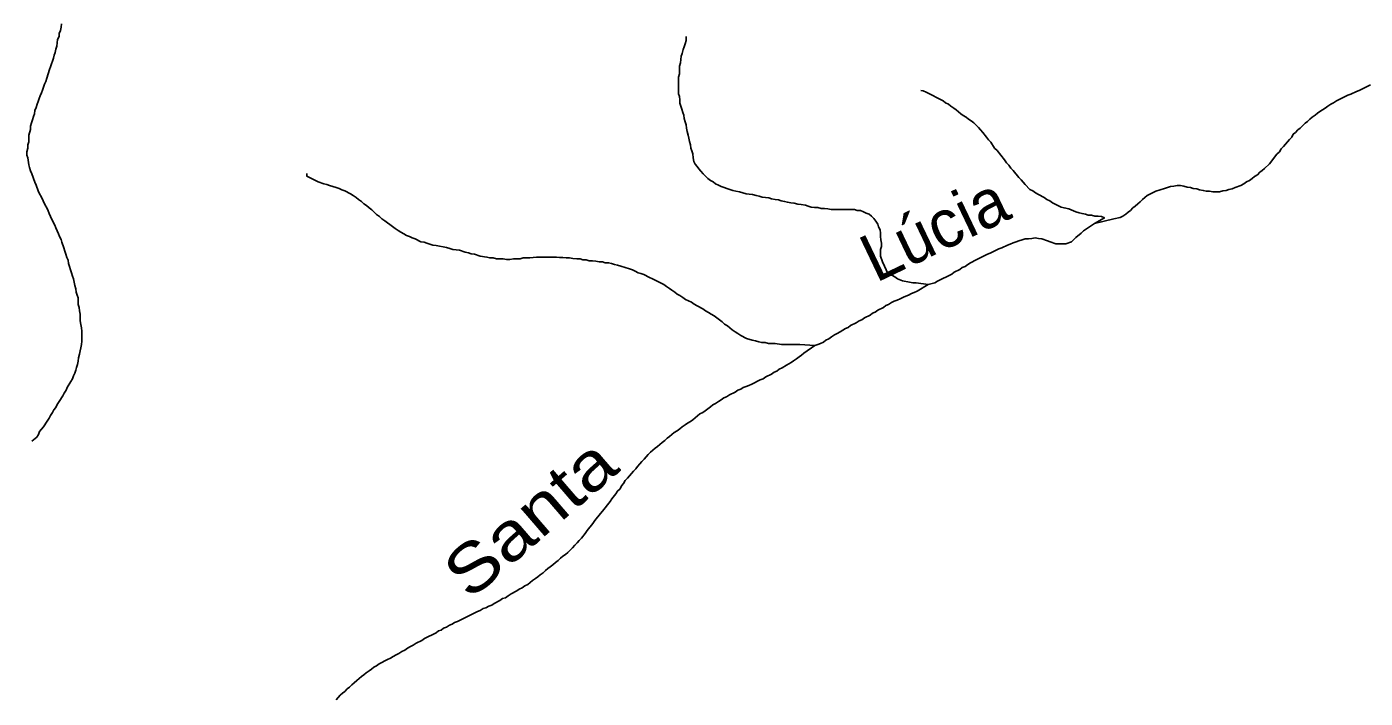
# Model space of a CAD drawing. Extents: x 652.3 to 678, y 7316.9 to 7344.9.
# Drawn here: x 670.317 to 672.557, y 7341.527 to 7342.649 of the extents above; entities that cross this region are included whole.
import ezdxf
from ezdxf.enums import TextEntityAlignment as Align

# ---------------------------------------------------------------- set-up
doc = ezdxf.new("R2010")
doc.units = 0
doc.header["$LTSCALE"] = 0.032
doc.layers.add('61', color=7, linetype='Continuous')
doc.layers.add('7', color=7, linetype='Continuous', lineweight=25)

msp = doc.modelspace()

# ---------------------------------------------------------------- linework, layer by layer
at = {"layer": '7'}
for points in [[(670.375, 7342.6543), (670.3742, 7342.6488), (670.3734, 7342.6432), (670.371, 7342.6384), (670.371, 7342.6329), (670.3686, 7342.6281), (670.3678, 7342.6225), (670.367, 7342.6169), (670.3654, 7342.6122), (670.3646, 7342.6066), (670.363, 7342.6018), (670.3614, 7342.597), (670.3567, 7342.5827), (670.3551, 7342.578), (670.3503, 7342.5636), (670.3487, 7342.5581), (670.3463, 7342.5533), (670.3447, 7342.5485)], [(671.4205, 7342.6333), (671.4205, 7342.6329), (671.4205, 7342.6313), (671.4205, 7342.6297), (671.4205, 7342.6281), (671.4205, 7342.6265), (671.4189, 7342.6209), (671.4173, 7342.6161), (671.4157, 7342.6114), (671.4141, 7342.605), (671.4125, 7342.6002), (671.4117, 7342.5947), (671.411, 7342.5891), (671.4094, 7342.5835), (671.4094, 7342.5764), (671.4094, 7342.5708), (671.4078, 7342.5652)], [(671.4078, 7342.5652), (671.4078, 7342.5596), (671.4078, 7342.5541), (671.4078, 7342.5485), (671.4078, 7342.5429), (671.4078, 7342.5374), (671.4094, 7342.5326), (671.4102, 7342.527), (671.4102, 7342.5215), (671.4117, 7342.5167), (671.4133, 7342.5119), (671.4149, 7342.5063), (671.4165, 7342.5016), (671.4173, 7342.496), (671.4189, 7342.4904), (671.4205, 7342.4857), (671.4213, 7342.4801), (671.4221, 7342.4745), (671.4237, 7342.4681), (671.4253, 7342.4634), (671.4261, 7342.4578), (671.4277, 7342.4522), (671.4285, 7342.4467), (671.43, 7342.4419), (671.4316, 7342.4371), (671.4324, 7342.43), (671.4332, 7342.4244), (671.4356, 7342.4196), (671.4388, 7342.4156), (671.442, 7342.4117), (671.4452, 7342.4077), (671.4491, 7342.4037), (671.4531, 7342.3997), (671.4571, 7342.3957), (671.4611, 7342.3926), (671.4659, 7342.3902), (671.4698, 7342.387), (671.4746, 7342.3846), (671.4794, 7342.3822), (671.4842, 7342.3806), (671.4889, 7342.379), (671.4937, 7342.3774), (671.4985, 7342.3758), (671.504, 7342.3743), (671.5096, 7342.3735), (671.5152, 7342.3719), (671.5208, 7342.3703), (671.5263, 7342.3695), (671.5319, 7342.3687), (671.5375, 7342.3671), (671.543, 7342.3663), (671.5478, 7342.3647), (671.5534, 7342.3639), (671.5589, 7342.3631), (671.5637, 7342.3615), (671.5693, 7342.3607), (671.5749, 7342.3599), (671.5796, 7342.3583), (671.5852, 7342.3575), (671.59, 7342.356), (671.5956, 7342.3552), (671.6011, 7342.3544), (671.6075, 7342.3528), (671.6131, 7342.352), (671.6202, 7342.3512), (671.625, 7342.3496), (671.6298, 7342.348), (671.6353, 7342.3472), (671.6409, 7342.3472), (671.6465, 7342.3456), (671.652, 7342.3456), (671.6576, 7342.3448), (671.6632, 7342.344), (671.6688, 7342.344), (671.6743, 7342.344), (671.6799, 7342.344), (671.6855, 7342.344), (671.691, 7342.344), (671.6966, 7342.344), (671.7022, 7342.344), (671.7069, 7342.3424), (671.7125, 7342.3424), (671.7173, 7342.34), (671.7221, 7342.3377), (671.7268, 7342.3361), (671.7308, 7342.3329), (671.7348, 7342.3289), (671.738, 7342.3241), (671.7412, 7342.3194), (671.7428, 7342.3146), (671.7451, 7342.3098), (671.7459, 7342.3042), (671.7459, 7342.2987), (671.7467, 7342.2931), (671.7475, 7342.2875), (671.7475, 7342.282), (671.7459, 7342.2772), (671.7459, 7342.2716), (671.7459, 7342.266), (671.7491, 7342.2565), (671.7587, 7342.2358)], [(670.3447, 7342.5485), (670.3431, 7342.5437), (670.3415, 7342.539), (670.3392, 7342.5342), (670.3376, 7342.5294), (670.336, 7342.5246), (670.3344, 7342.5199), (670.3328, 7342.5143), (670.3304, 7342.5095), (670.3296, 7342.504), (670.328, 7342.4992), (670.3264, 7342.4936), (670.3248, 7342.4888), (670.3232, 7342.4833), (670.3232, 7342.4777), (670.3201, 7342.4681), (670.3201, 7342.457), (670.3185, 7342.4522), (670.3185, 7342.4467), (670.3169, 7342.4403), (670.3169, 7342.4347), (670.3185, 7342.43), (670.3201, 7342.4188), (670.3217, 7342.414), (670.3232, 7342.4085), (670.3256, 7342.4037), (670.3304, 7342.3894), (670.3328, 7342.3846), (670.336, 7342.375), (670.3384, 7342.3703), (670.3408, 7342.3655), (670.3479, 7342.3512), (670.3503, 7342.3464), (670.3527, 7342.3416), (670.3543, 7342.3369), (670.3567, 7342.3321), (670.3591, 7342.3273), (670.3638, 7342.3178), (670.3654, 7342.313), (670.3678, 7342.3082), (670.3702, 7342.3034), (670.3718, 7342.2987), (670.3742, 7342.2939), (670.3758, 7342.2891), (670.3789, 7342.2796), (670.3805, 7342.274), (670.3821, 7342.2692), (670.3837, 7342.2637), (670.3861, 7342.2589), (670.3869, 7342.2533), (670.3885, 7342.2485), (670.3901, 7342.243), (670.3917, 7342.2382), (670.3933, 7342.2326), (670.3949, 7342.2278), (670.3964, 7342.2223), (670.3972, 7342.2167), (670.3988, 7342.2111), (670.3996, 7342.2056), (670.4012, 7342.2008), (670.4028, 7342.196), (670.4028, 7342.1849), (670.4044, 7342.1801), (670.4052, 7342.1745), (670.406, 7342.169), (670.406, 7342.1578), (670.4076, 7342.1515), (670.4084, 7342.1459), (670.4092, 7342.1403), (670.4092, 7342.1236), (670.4084, 7342.118), (670.4076, 7342.1125), (670.406, 7342.1077), (670.4052, 7342.1021), (670.4036, 7342.0958), (670.4028, 7342.0902), (670.402, 7342.0846), (670.4004, 7342.0798), (670.3988, 7342.0751), (670.3972, 7342.0703), (670.3949, 7342.0655), (670.3933, 7342.0608), (670.3909, 7342.056), (670.3845, 7342.0464), (670.3829, 7342.0417), (670.3797, 7342.0369), (670.3774, 7342.0321), (670.371, 7342.0226), (670.3678, 7342.0178), (670.3654, 7342.013), (670.3622, 7342.009), (670.3598, 7342.0043), (670.3567, 7341.9995), (670.3543, 7341.9947), (670.3511, 7341.9899), (670.3447, 7341.9804), (670.3384, 7341.9724), (670.3368, 7341.9677), (670.3336, 7341.9629), (670.3256, 7341.9565), (670.3253, 7341.9563)], [(672.1041, 7342.3206), (672.1207, 7342.3297), (672.1159, 7342.3321), (672.1104, 7342.3329), (672.1048, 7342.3329), (672.0992, 7342.3345), (672.0937, 7342.3345), (672.0889, 7342.3361), (672.0833, 7342.3369), (672.0785, 7342.3384), (672.073, 7342.34), (672.061, 7342.3448), (672.0531, 7342.3464), (672.0483, 7342.348), (672.034, 7342.3552), (672.0292, 7342.3583), (672.0244, 7342.3607), (672.0197, 7342.3639), (672.0101, 7342.3687), (672.0053, 7342.3719), (672.0006, 7342.375), (671.9958, 7342.3774), (671.9878, 7342.3854), (671.9846, 7342.3894), (671.9815, 7342.3934), (671.9775, 7342.3973), (671.9679, 7342.4093), (671.964, 7342.4132), (671.9608, 7342.418), (671.9568, 7342.422), (671.9536, 7342.4268), (671.9409, 7342.4427), (671.9369, 7342.4467), (671.9305, 7342.4562), (671.9266, 7342.4602), (671.9234, 7342.465), (671.917, 7342.4729), (671.913, 7342.4769), (671.9098, 7342.4809), (671.9059, 7342.4849), (671.9019, 7342.4888), (671.8979, 7342.492), (671.8931, 7342.4952), (671.8892, 7342.4984), (671.8844, 7342.5008), (671.8804, 7342.504), (671.8764, 7342.5071), (671.8725, 7342.5103), (671.8685, 7342.5135), (671.8637, 7342.5167), (671.8597, 7342.5199), (671.8549, 7342.5223), (671.851, 7342.5254), (671.8223, 7342.5398), (671.8175, 7342.5421), (671.8136, 7342.5429), (671.8132, 7342.543)], [(672.1041, 7342.3206), (672.1366, 7342.3281), (672.147, 7342.3305), (672.1517, 7342.3329), (672.1565, 7342.3361), (672.1605, 7342.3392), (672.1645, 7342.3424), (672.1684, 7342.3464), (672.1724, 7342.3496), (672.1764, 7342.3536), (672.1804, 7342.3567), (672.1844, 7342.3607), (672.1883, 7342.3639), (672.1923, 7342.3671), (672.2066, 7342.3743), (672.221, 7342.379), (672.2265, 7342.3806), (672.2313, 7342.3822), (672.2369, 7342.383), (672.2424, 7342.3838), (672.248, 7342.3838), (672.2536, 7342.383), (672.2592, 7342.3814), (672.2647, 7342.3806), (672.2695, 7342.379), (672.2751, 7342.3782), (672.2798, 7342.3766), (672.2862, 7342.3758), (672.291, 7342.3743), (672.2966, 7342.3743), (672.3021, 7342.3735), (672.3133, 7342.3735), (672.3188, 7342.375), (672.3244, 7342.3758), (672.3292, 7342.3774), (672.3347, 7342.3782), (672.3395, 7342.3806), (672.3491, 7342.3838), (672.3538, 7342.387), (672.3586, 7342.3902), (672.3634, 7342.3926), (672.3682, 7342.3957), (672.3721, 7342.3989), (672.3769, 7342.4021), (672.3809, 7342.4061), (672.3849, 7342.4093), (672.3889, 7342.4124), (672.3968, 7342.4204), (672.4095, 7342.4363), (672.4135, 7342.4403), (672.4167, 7342.4451), (672.4207, 7342.449), (672.4239, 7342.453), (672.427, 7342.457), (672.4302, 7342.461), (672.4342, 7342.465), (672.4366, 7342.4697), (672.4406, 7342.4729), (672.4446, 7342.4769), (672.4485, 7342.4801), (672.4565, 7342.488), (672.4605, 7342.4912), (672.4644, 7342.4952), (672.4684, 7342.4984), (672.4732, 7342.5016), (672.4772, 7342.5047), (672.4812, 7342.5079), (672.4859, 7342.5103), (672.4899, 7342.5135), (672.4947, 7342.5167), (672.4995, 7342.5199), (672.5042, 7342.5223), (672.509, 7342.5254), (672.5281, 7342.535), (672.5329, 7342.5366), (672.5424, 7342.5413), (672.5472, 7342.5429), (672.5663, 7342.5525)], [(670.7855, 7342.4041), (670.7855, 7342.3997), (670.8046, 7342.3902), (670.8142, 7342.387), (670.819, 7342.3854), (670.8237, 7342.3838), (670.8349, 7342.3806), (670.8396, 7342.379), (670.8444, 7342.3766), (670.8492, 7342.375), (670.8587, 7342.3703), (670.8635, 7342.3671), (670.8683, 7342.3639), (670.8723, 7342.3607), (670.877, 7342.3575), (670.881, 7342.3536), (670.8858, 7342.3504), (670.8898, 7342.3464), (670.8945, 7342.3432), (670.9025, 7342.3353), (670.9073, 7342.3321), (670.9113, 7342.3281), (670.916, 7342.3249), (670.9208, 7342.3217), (670.9248, 7342.3186), (670.9288, 7342.3154), (670.9335, 7342.3122), (670.9383, 7342.309), (670.9431, 7342.3058), (670.9479, 7342.3034), (670.9526, 7342.3003), (670.9574, 7342.2987), (670.9622, 7342.2963)], [(671.8255, 7342.2183), (671.8366, 7342.2215), (671.8414, 7342.2239), (671.8653, 7342.2358), (671.8693, 7342.239), (671.8788, 7342.2438), (671.8828, 7342.2469), (671.8876, 7342.2485), (671.8923, 7342.2517), (671.8963, 7342.2549), (671.9059, 7342.2597), (671.9106, 7342.2621), (671.925, 7342.2692), (671.9297, 7342.2708), (671.9441, 7342.278), (671.9488, 7342.2796), (671.9584, 7342.2843), (671.9632, 7342.2859), (671.9679, 7342.2883), (671.9727, 7342.2899), (671.9775, 7342.2915), (671.9831, 7342.2931), (671.9878, 7342.2947), (671.9934, 7342.2947), (671.999, 7342.2955), (672.0045, 7342.2963), (672.0101, 7342.2955), (672.0157, 7342.2947), (672.0252, 7342.2915), (672.03, 7342.2899), (672.0395, 7342.2867), (672.0563, 7342.2867), (672.0658, 7342.2899), (672.073, 7342.2971), (672.0817, 7342.3042), (672.0857, 7342.3082), (672.1041, 7342.3206)], [(670.9622, 7342.2963), (670.967, 7342.2947), (670.9765, 7342.2899), (670.9821, 7342.2891), (670.9868, 7342.2875), (670.9964, 7342.2843), (671.002, 7342.2835), (671.0075, 7342.2828), (671.0139, 7342.2812), (671.0195, 7342.2804), (671.025, 7342.2788), (671.0298, 7342.2772), (671.0354, 7342.2764), (671.041, 7342.2756), (671.0505, 7342.2724), (671.0561, 7342.2716), (671.0608, 7342.27), (671.0664, 7342.2692), (671.076, 7342.266), (671.0871, 7342.2644), (671.0919, 7342.2629), (671.0975, 7342.2629), (671.103, 7342.2613), (671.1142, 7342.2613), (671.1197, 7342.2605), (671.1253, 7342.2605), (671.1317, 7342.2613), (671.1428, 7342.2613), (671.1476, 7342.2629), (671.1587, 7342.2629), (671.1643, 7342.2637), (671.1699, 7342.2644), (671.2033, 7342.2644), (671.2088, 7342.2637), (671.2144, 7342.2637), (671.22, 7342.2629), (671.2256, 7342.2629), (671.2311, 7342.2621), (671.2375, 7342.2613), (671.2431, 7342.2613), (671.2478, 7342.2597), (671.2534, 7342.2597), (671.2582, 7342.2581), (671.2637, 7342.2581), (671.2693, 7342.2573), (671.2749, 7342.2565), (671.2805, 7342.2565), (671.2852, 7342.2549), (671.2908, 7342.2549), (671.2956, 7342.2533), (671.3004, 7342.2517), (671.3059, 7342.2509), (671.3115, 7342.2493), (671.3258, 7342.2446), (671.3306, 7342.243), (671.3354, 7342.2406), (671.3401, 7342.2382), (671.3449, 7342.2366), (671.3497, 7342.235), (671.3592, 7342.2302), (671.364, 7342.2278), (671.3831, 7342.2183), (671.3879, 7342.2151), (671.3927, 7342.2119), (671.3966, 7342.2088), (671.4014, 7342.2056), (671.4054, 7342.2024), (671.4102, 7342.2), (671.4149, 7342.1968), (671.4197, 7342.1936), (671.4293, 7342.1889), (671.434, 7342.1857), (671.4388, 7342.1825), (671.4483, 7342.1777), (671.4531, 7342.1745), (671.4579, 7342.1714), (671.4627, 7342.169), (671.4674, 7342.1658), (671.4722, 7342.1626), (671.4762, 7342.1594), (671.481, 7342.1562), (671.485, 7342.1523), (671.4897, 7342.1491), (671.4937, 7342.1459), (671.4977, 7342.1427), (671.5025, 7342.1395), (671.5072, 7342.1363), (671.512, 7342.1332), (671.5216, 7342.1284), (671.5311, 7342.1252), (671.5367, 7342.1244), (671.5422, 7342.1228), (671.547, 7342.1212), (671.5526, 7342.1212), (671.5582, 7342.1196), (671.5693, 7342.1196), (671.5804, 7342.118), (671.5884, 7342.118), (671.5995, 7342.118), (671.6107, 7342.118), (671.6361, 7342.1165)], [(671.6361, 7342.1165), (671.6409, 7342.118), (671.6457, 7342.1196), (671.6505, 7342.122), (671.6544, 7342.1252), (671.6592, 7342.1276), (671.664, 7342.1308), (671.6688, 7342.134), (671.6735, 7342.1363), (671.6783, 7342.1395), (671.6831, 7342.1419), (671.6871, 7342.1451), (671.6918, 7342.1467), (671.6958, 7342.1499), (671.7054, 7342.1546), (671.7101, 7342.1578), (671.7149, 7342.1594), (671.7189, 7342.1626), (671.7284, 7342.1674), (671.7324, 7342.1706), (671.7372, 7342.1721), (671.7412, 7342.1753), (671.7507, 7342.1801), (671.7547, 7342.1833), (671.7595, 7342.1849), (671.7642, 7342.1881), (671.769, 7342.1905), (671.7738, 7342.192), (671.7786, 7342.1944), (671.7857, 7342.1976), (671.7929, 7342.2008), (671.7977, 7342.2032), (671.8024, 7342.2048), (671.8072, 7342.2072), (671.8255, 7342.2183)], [(671.7587, 7342.2358), (671.765, 7342.2342), (671.7698, 7342.231), (671.7746, 7342.2278), (671.7825, 7342.2247), (671.7945, 7342.2223), (671.8, 7342.2215), (671.8056, 7342.2215), (671.8255, 7342.2183)], [(671.146, 7341.7114), (671.1508, 7341.7146), (671.1555, 7341.717), (671.1595, 7341.7202), (671.1635, 7341.7234), (671.1683, 7341.7266), (671.1722, 7341.7297), (671.1762, 7341.7329), (671.181, 7341.7361), (671.185, 7341.7401), (671.189, 7341.7433), (671.1929, 7341.7465), (671.1977, 7341.7496), (671.2017, 7341.7536), (671.2065, 7341.7568), (671.2104, 7341.7608), (671.2144, 7341.764), (671.2184, 7341.7671), (671.2224, 7341.7703), (671.2303, 7341.7783), (671.2343, 7341.7823), (671.2383, 7341.7862), (671.2415, 7341.7902), (671.2454, 7341.7942), (671.2518, 7341.8022), (671.255, 7341.8069), (671.2645, 7341.8189), (671.2677, 7341.8236), (671.2773, 7341.8356), (671.2805, 7341.8396), (671.2932, 7341.8555), (671.2964, 7341.8602), (671.3027, 7341.8682), (671.3059, 7341.873), (671.3099, 7341.8769), (671.3123, 7341.8817), (671.3155, 7341.8857), (671.3187, 7341.8905), (671.3226, 7341.8945), (671.3322, 7341.9064), (671.3362, 7341.9104), (671.3393, 7341.9143), (671.3433, 7341.9183), (671.3465, 7341.9223), (671.3505, 7341.9263), (671.3568, 7341.9342), (671.3608, 7341.9382), (671.3648, 7341.9414), (671.3688, 7341.9446), (671.3728, 7341.9478), (671.3767, 7341.9509), (671.3807, 7341.9541), (671.3847, 7341.9573), (671.3887, 7341.9613), (671.3927, 7341.9645), (671.3966, 7341.9677), (671.4006, 7341.9708), (671.4054, 7341.974), (671.4102, 7341.9772), (671.4141, 7341.9804), (671.4189, 7341.9836), (671.4229, 7341.9868), (671.4277, 7341.9891), (671.4316, 7341.9923), (671.4356, 7341.9955), (671.4396, 7341.9987), (671.4436, 7342.0019), (671.4483, 7342.0043), (671.4523, 7342.0074), (671.4571, 7342.0106), (671.4611, 7342.0138), (671.4651, 7342.017), (671.4698, 7342.0194), (671.4746, 7342.0226), (671.4794, 7342.0257), (671.4834, 7342.0289), (671.4881, 7342.0305), (671.4929, 7342.0337), (671.5025, 7342.0385), (671.5072, 7342.0417), (671.512, 7342.0432), (671.516, 7342.0464), (671.5208, 7342.048), (671.5255, 7342.0496), (671.5303, 7342.052), (671.5446, 7342.0592), (671.5494, 7342.0608), (671.5542, 7342.0639), (671.5637, 7342.0687), (671.5677, 7342.0719), (671.5725, 7342.0735), (671.5765, 7342.0767), (671.5812, 7342.0791), (671.5884, 7342.0838), (671.5963, 7342.0878), (671.6003, 7342.091), (671.6051, 7342.0942), (671.6099, 7342.0974), (671.6139, 7342.1005), (671.6178, 7342.1037), (671.6361, 7342.1165)], [(670.8349, 7341.5237), (670.8381, 7341.5276), (670.8412, 7341.5316), (670.8452, 7341.5348), (670.8492, 7341.538), (670.8532, 7341.542), (670.8572, 7341.5451), (670.8611, 7341.5491), (670.8651, 7341.5523), (670.8691, 7341.5563), (670.8731, 7341.5595), (670.877, 7341.5627), (670.881, 7341.5658), (670.885, 7341.569), (670.8898, 7341.5722), (670.8938, 7341.5754), (670.8977, 7341.5786), (670.9025, 7341.581), (670.9065, 7341.5841), (670.9208, 7341.5913), (670.9256, 7341.5937), (670.9304, 7341.5961), (670.9351, 7341.5993), (670.9399, 7341.6016), (670.9447, 7341.6048), (670.9495, 7341.6072), (670.9542, 7341.6104), (670.959, 7341.6128), (670.9638, 7341.6152), (670.9685, 7341.6184), (670.9781, 7341.6231), (670.9829, 7341.6263), (671.002, 7341.6359), (671.0059, 7341.639), (671.0107, 7341.6406), (671.0147, 7341.6438), (671.0195, 7341.6454), (671.0242, 7341.6486), (671.029, 7341.6502), (671.033, 7341.6534), (671.0378, 7341.655), (671.0425, 7341.6573), (671.0712, 7341.6717), (671.076, 7341.6733), (671.0807, 7341.6764), (671.0855, 7341.678), (671.0903, 7341.6804), (671.0951, 7341.682), (671.099, 7341.6852), (671.1086, 7341.69), (671.1134, 7341.6931), (671.1181, 7341.6947), (671.1229, 7341.6979), (671.1277, 7341.7011), (671.1372, 7341.7059), (671.1412, 7341.7091), (671.146, 7341.7114)]]:
    msp.add_lwpolyline(points, dxfattribs=at)

# ---------------------------------------------------------------- texts
at = {"layer": '61'}
msp.add_text('Lúcia', height=0.08, rotation=25.553, dxfattribs=at).set_placement((671.8534, 7342.2758), align=Align.CENTER)
at = {"layer": '61', "width": 1.2}
msp.add_text('Santa', height=0.08, rotation=40.793, dxfattribs=at).set_placement((671.1852, 7341.7984), align=Align.CENTER)

doc.saveas('drawing.dxf')
